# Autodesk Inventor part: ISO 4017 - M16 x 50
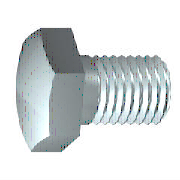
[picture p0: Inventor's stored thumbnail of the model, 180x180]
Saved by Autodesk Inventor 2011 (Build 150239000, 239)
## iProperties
Created: 2010-02
Part Number: ISO 4017 - M16 x 50
Material: Stainless Steel, 440C
Description: Hexagon head screws
Document SubType Name: Modeling
Standard: ISO 4017
Designer: 129877
Standard Revision: Third edition 1999-08-15
Standards Organization: ISO
Language: en-US
Size Designation: M16 x 50
Categories: <MemberInstance><Categories><Category DisplayName="Fasteners" InternalName="e4da775c-781d-43d5-af7c-5136215cf5a6" Mnemonic="FSTN"><Category DisplayName="Bolts"
Density: 7.75 g/cm^3
Mass: 115.547 g
Surface Area: 42.7087 cm^2
Volume: 14.9093 cm^3
IsCustomPart: 0
Author: 129877
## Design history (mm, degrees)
body "Solid1"
workplane "Work Plane1"
revolve "Body" stored, may be unused: angle "d12" = 90 deg
sketch "Sketch2"
  geometry: L1 (0, 13.856)-(12, 6.928); L2 (12, 6.928)-(12, -6.928); L3 (12, -6.928)-(0, -13.856); L4 (0, -13.856)-(-12, -6.928); L5 (-12, -6.928)-(-12, 6.928); L6 (-12, 6.928)-(0, 13.856); 2 further points
  constraints: 12 end point, 1 coincident, 1 vertical, 11 other
  dimensions: "d11" = 24 distance between parallel lines of L5 L2 (= SW)
extrude "Head" join sketch "Sketch2" distance "d3" = 9.2 (= KOH - SD); taper "d4" = 0 deg
revolve "Chamfer1" stored, may be unused: angle "d21" = 90 deg
feature "Thread" dims "d15" = 44 (= GEL), "d16" = 0
chamfer "Chamfer2" distance "d6" = 1.2269 (= -0.5 x SPD + 0.5 x GD); stored, may be unused: second distance "d7" = 1.227 (computed from GUL), angle "d55" = 45 deg
sketch "Sketch1"
  geometry: L1 (0, 11.245)-(0, 8); L2 (6, 8)-(50, 8); L3 (50, 8)-(50, 0); L4 (50, 0)-(-0.8, 0); L5 (-10.96, 0)-(60.16, 0) reference; L6 (-0.8, 0)-(-0.8, 11.245); L7 (-0.8, 11.245)-(0, 11.245); L8 (6, 8)-(4.773, 8); L9 (4.773, 8)-(0, 8); L10 (0, -2.249)-(0, 13.494) reference
  constraints: 16 end point, 2 collinear, 2 perpendicular, 1 parallel
  dimensions: "d0" = 50 distance between parallel lines of L3 L1 (= NLG); "d1" = 44 distance from line of L2.start L3 (= GEL); "d2" = 16 diameter of L2 L4 (= GD); "d9" = 0.8001 distance between parallel lines of L6 L1 (computed from SD); "d10" = 22.49 diameter of L7 L4 (= SD2); "d13" = 1.227 distance of L2.start L8.end (computed from GAL); "d14" = 16 diameter of L9 L4 (= BDM)
sketch "Sketch4"
  geometry: L1 (-10, 12)-(-10, 13.856); L2 (-10, 13.856)-(-8.928, 13.856); L3 (-8.928, 13.856)-(-10, 12); L4 (-11.84, 0)-(1.04, 0) reference; L5 (-0.8, 13.856)-(-10, 13.856) reference; L6 (-10, 6.928)-(-10, 13.856) reference
  constraints: 6 end point, 2 collinear, 1 perpendicular, 1 vertical
  dimensions: "d5" = 30 deg angle of L3 L1 (= ANG1); "d19" = 24 diameter of L1.start L4 (= SW0)
other parameters: "NLG" = 50 [user parameter; used in 1 equation term], "GD" = 16 (= NND) [user parameter; used in 2 equation terms], "BDM" = 16 (= NND) [user parameter; used in 1 equation term], "KOH" = 10 [user parameter; used in 1 equation term], "GEL" = 44 [user parameter; used in 2 equation terms], "SW" = 24 [user parameter; used in 2 equation terms], "SW0" = 24 (= SW) [user parameter; used in 1 equation term], "SPD" = 13.5462 (= NND - 1.2269 x PTC) [user parameter; used in 1 equation term], "SD2" = 22.49 [user parameter; used in 2 equation terms], "SD" = 0.8 [user parameter; used in 2 equation terms], "ANG1" = 30 deg [user parameter; used in 1 equation term], "GAL" = 1.2269 (= 0.61345 x PTC) [user parameter; used in 1 equation term], "GUL" = 1.2269 (= 0.61345 x PTC) [user parameter; used in 1 equation term], "d8" = 0, "RR" = 0.6 [user parameter], "d57" = 0, "d58" = 0, "TPU" = 5 (computed from PTC) [user parameter], "GD1" = 13.5462 (= THREADDIA - 1.2269 x PTC) [user parameter], "THREADDIA" = 16 [user parameter; used in 1 equation term], "SDH" = 22.49 (= SD2) [user parameter], "SDHG" = 6 [user parameter], "TOA" = 30 deg [user parameter], "PTC" = 2 [user parameter; used in 5 equation terms], "NND" = 16 [user parameter; used in 3 equation terms], "E0" = 27.72 [user parameter]
